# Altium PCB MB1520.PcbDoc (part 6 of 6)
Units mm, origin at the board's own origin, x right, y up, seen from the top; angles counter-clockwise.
Board outline 159 x 88 mm, 6 copper layers (Top Layer, Signal Layer 1, Signal Layer 2, Signal Layer 3, Signal Layer 4, Bottom Layer), stack 1.572 mm thick; 473 components, 377 nets, 1832 pads, 1378 vias.
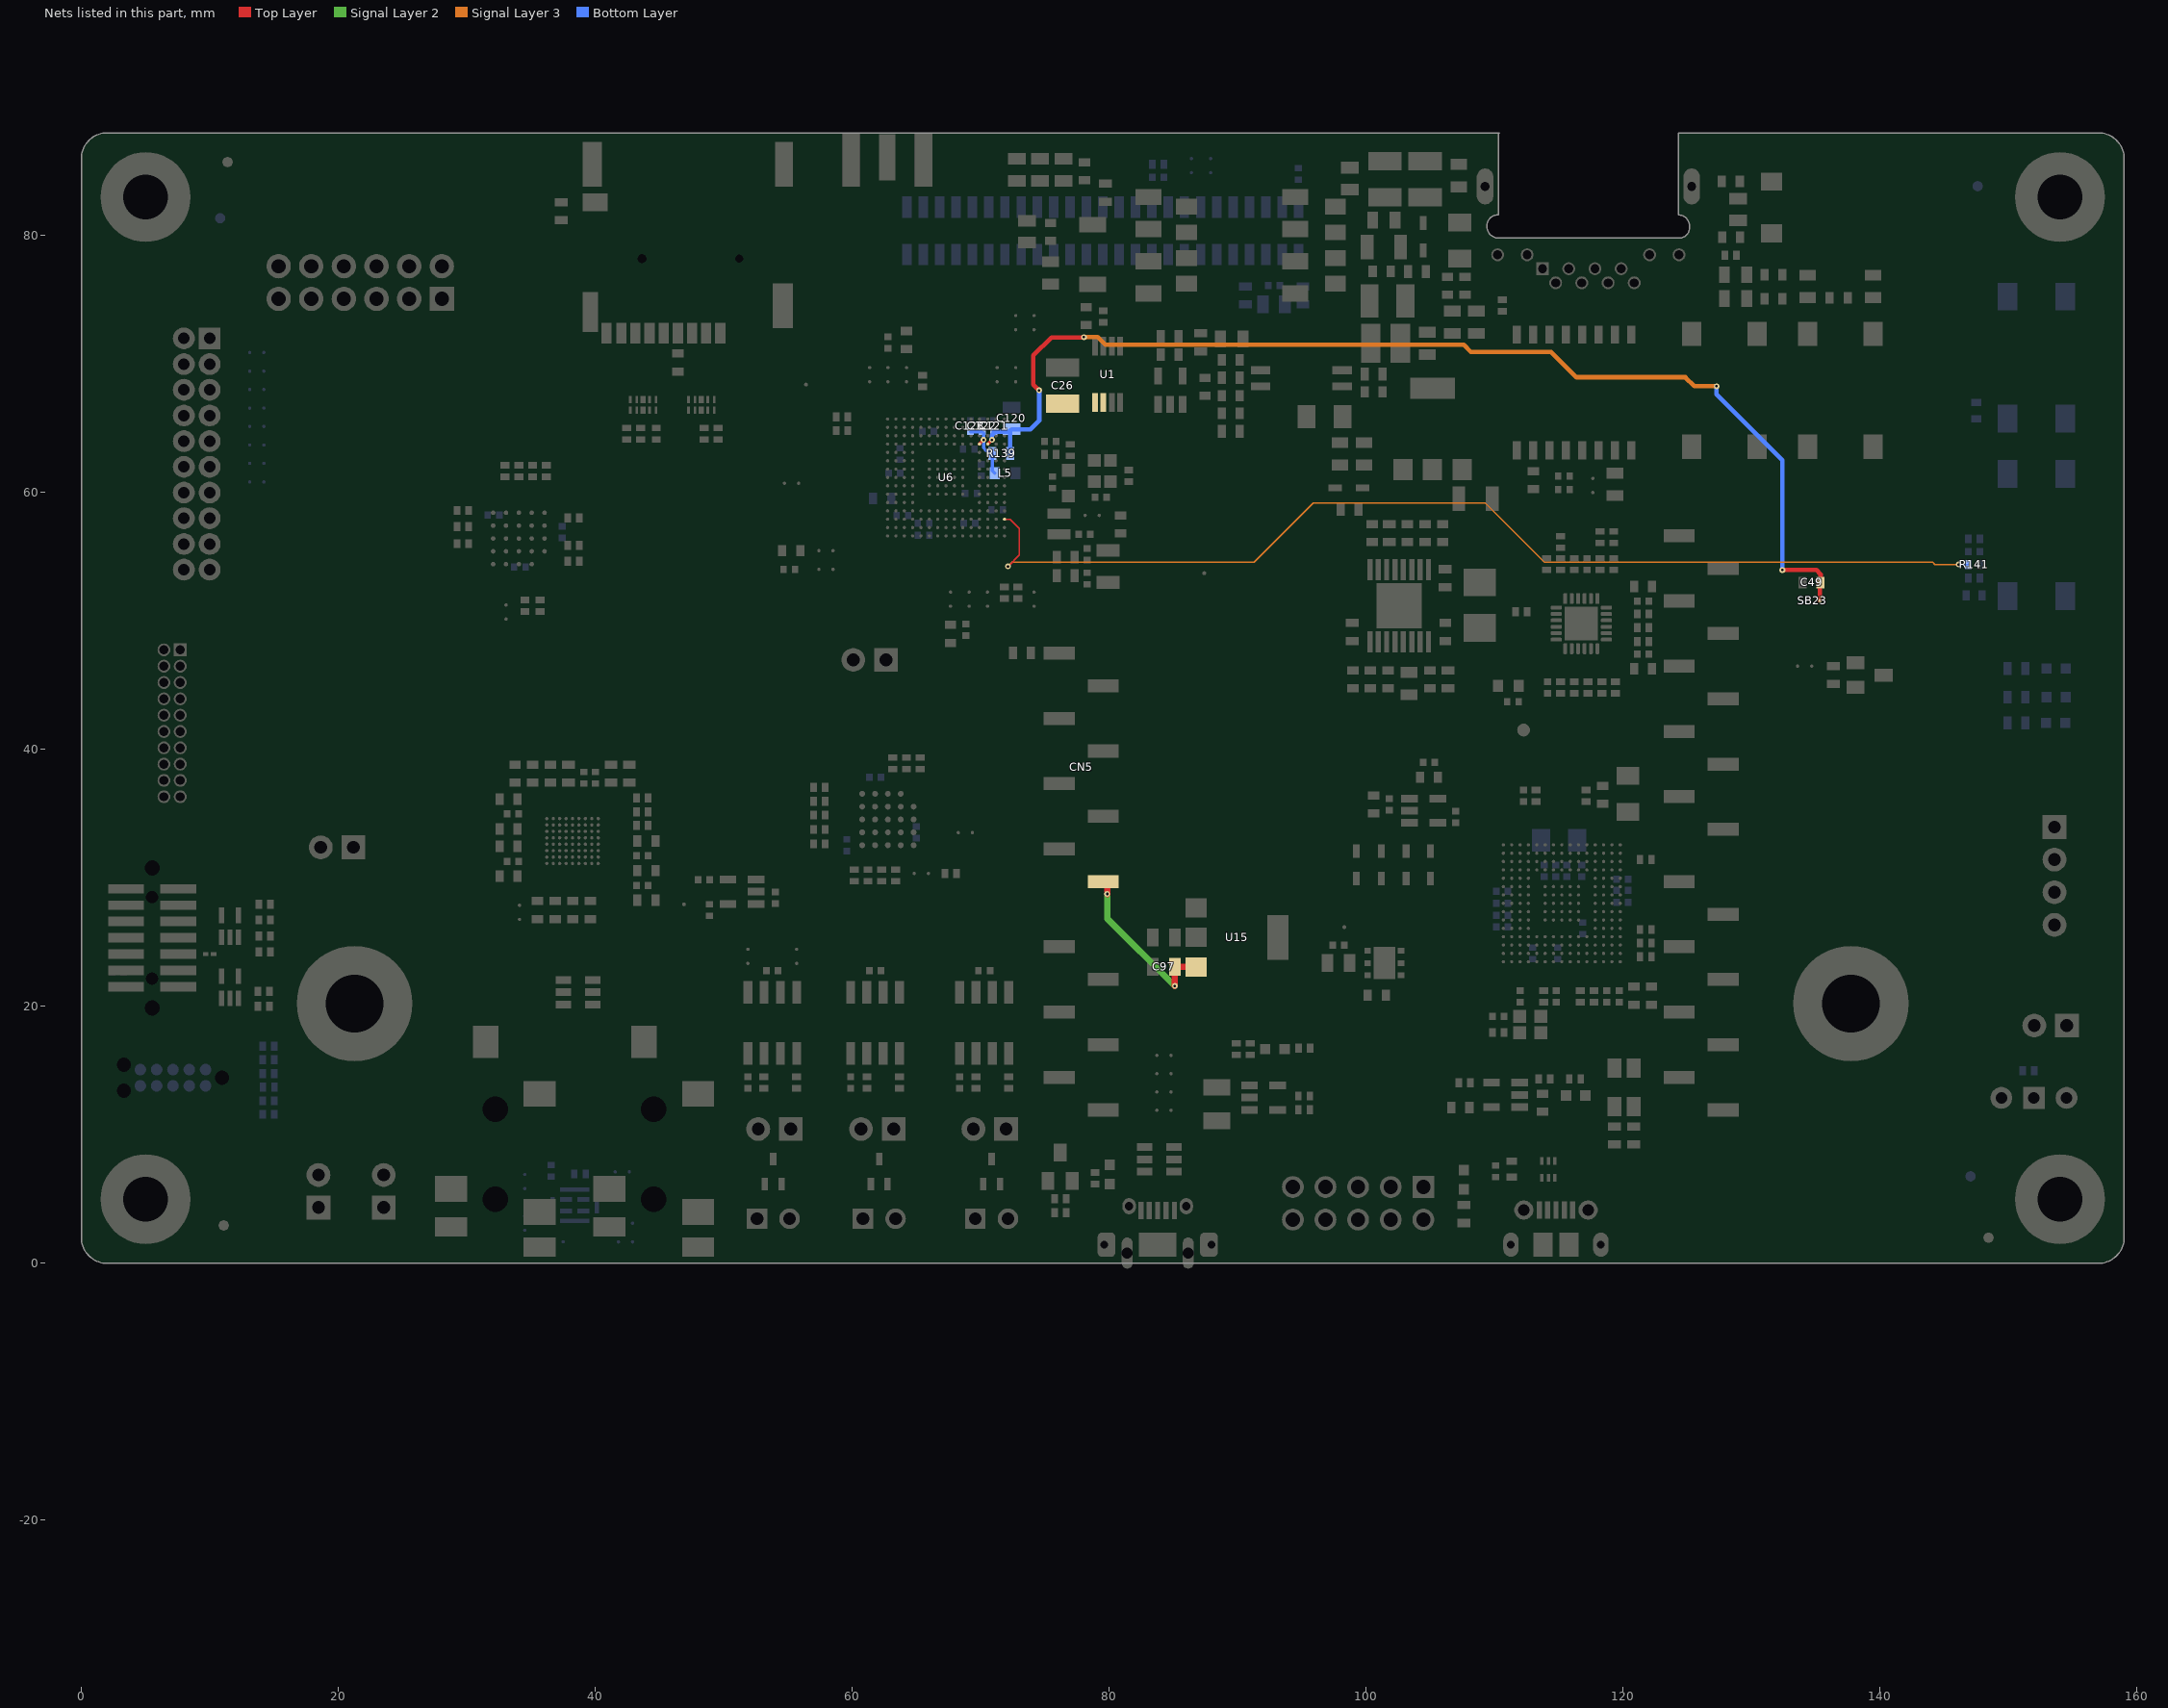
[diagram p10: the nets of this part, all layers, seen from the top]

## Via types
v1: diameter 0.45, hole 0.2, Top Layer to Bottom Layer, tented both sides, 1099 vias
v2: diameter 0.25, hole 0.1, Top Layer to Signal Layer 1, tented both sides, 217 vias
v3: diameter 0.25, hole 0.1, Signal Layer 4 to Bottom Layer, tented both sides, 53 vias
v4: diameter 0.6, hole 0.3, Top Layer to Bottom Layer, tented both sides, 9 vias

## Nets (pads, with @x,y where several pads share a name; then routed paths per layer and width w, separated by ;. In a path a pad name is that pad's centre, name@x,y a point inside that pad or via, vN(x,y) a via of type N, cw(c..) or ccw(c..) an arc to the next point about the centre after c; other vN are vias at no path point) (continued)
VDDA: C122.2 C123.1 L5.2 R139.2 U6.M4 | length 5.2
  Top Layer w0.25: U6.M4@69.9,63.775 v1(70.225,64.1)
  Bottom Layer w0.25: C123.1@69.2,64.725 C122.2@70.125,64.725 70.225,64.625 v1(70.225,64.1) 70.225,63.475 70.432,63.268 70.682,63.268 R139.2@70.9,63.05 70.9,61.7 L5.2@71.1,61.5
VIN: C97.2 CN5.8 U15.3 | length 14
  Top Layer w0.508: CN5.8@79.54,29.72 79.85,29.411 v1(79.85,28.75) ; v1(85.1,21.596) C97.2@85.1,23.475 ; C97.2@85.1,23.075 U15.3@86.775,23.075
  Signal Layer 2 w0.508: v1(79.85,28.75) 79.85,26.846 v1(85.1,21.596)
VREF+: C26.2 C49.2 C120.2 C121.2 R139.1 SB23.2 U1.5 U1.6 U6.M3 | length 89
  Top Layer w0.25: U6.M3@70.55,63.775 v1(70.875,64.1)
  Top Layer w0.35: v1(74.55,67.95) 74.1,68.4 74.1,70.675 75.5,72.075 78,72.075 v1(78.025,72.1) ; v1(132.4,53.975) 135.05,53.975 135.375,53.65 C49.2@135.375,53 135.325,52.95 SB23.2@135.325,51.575
  Signal Layer 3 w0.35: v1(78.025,72.1) 79.1,72.1 79.7,71.5 107.6,71.5 108.15,70.95 114.4,70.95 116.375,68.975 124.85,68.975 125.55,68.275 v1(127.275,68.275)
  Bottom Layer w0.35: v1(70.875,64.1) 70.875,64.45 71.025,64.6 C121.2@71.025,64.725 72.2,64.725 C120.2@72.3,64.825 ; R139.1@72.3,63.05 C120.2@72.3,64.825 ; v1(74.55,67.95) 74.55,65.6 73.875,64.925 C120.2@72.4,64.925 C120.2@72.3,64.825 ; v1(127.275,68.275) 127.275,67.65 132.4,62.525 v1(132.4,53.975)
WAKEUP: R141.2 U6.C1 | length 83.5
  Top Layer w0.1: U6.C1@71.85,57.925 72.275,57.925 73,57.2 73,55.125 v1(72.125,54.25)
  Signal Layer 3 w0.12: v1(72.125,54.25) 72.45,54.575 91.275,54.575 95.875,59.175 109.275,59.175 113.875,54.575 144.1,54.575 144.275,54.4 v1(146.125,54.4)
  Bottom Layer w0.12: v1(146.125,54.4) R141.2@146.875,54.4
pads on no net: CN2.NPTH1 CN2.NPTH2 CN7.0 CN7.1 CN7.2 CN7.9 CN10.2 CN10.5 CN10.7 CN10.MT1 CN10.MT2 CN11.2 CN11.5 CN11.7 CN11.MT1 CN11.MT2 CN14.11 CN14.12 CN15.4 CN19.41 CN19.42 CN19.44 CN19.46 CN19.48 CN20.8 CN20.9 CN20.11 CN20.13 CN20.14 CN20.15 CN20.16 CN20.17 CN20.18 CN21.7 CN21.11 CN21.12 CN21.13 MIRE1.1 MIRE4.1 MIRE5.1 MIRE6.1 MIRE7.1 MIRE8.1 P1.9 P1.10 T3.4 T3.5 T3.12 T3.13 U3.1 U3.2 U5.4 U5.5 U5.6 U5.7 U7.A2 U7.A5 U7.B5 U7.C2 U7.C5 U9.4 U10.A2 U10.A3 U10.B1 U10.B5 U10.C5 U12.A6 U12.A8 U12.B4 U12.B5 U12.B8 U12.B9 U12.C4 U12.C5 U12.C7 U12.C8 U12.E1 U12.E5 U12.F4 U12.F5 U12.F6 U12.F8 U12.F9 U12.G4 U12.H2 U12.H3 U12.H4 U12.H5 U13.A1 U13.A2 U13.A3 U13.A4 U13.A5 U13.A6 U13.A8 U13.A9 U13.A10 U13.A11 U13.A12 U13.A13 U13.B1 U13.B2 U13.B3 U13.B4 U13.B5 U13.B6 U13.B7 U13.B8 U13.B9 U13.B10 U13.B11 U13.B12 U13.B13 U13.B14 U13.B15 U13.C2 U13.C3 U13.C4 U13.C11 U13.C12 U13.C13 U13.C14 U13.C15 U13.D1 U13.D2 U13.D3 U13.D4 U13.D10 U13.D11 U13.D13 U13.D14 U13.E1 U13.E2 U13.E3 U13.E4 U13.E12 U13.E13 U13.E14 U13.E15 U13.F1 U13.F4 U13.F14 U13.G4 U13.G14 U13.G15 U13.H1 U13.H2 U13.H3 U13.H4 U13.H14 U13.H15 U13.J2 U13.J3 U13.J4 U13.K1 U13.K2 U13.K3 U13.K12 U13.K14 U13.K15 U13.L1 U13.L3 U13.L12 U13.L13 U13.L14 U13.L15 U13.M2 U13.M3 U13.M4 U13.M5 U13.M6 U13.M7 U13.M12 U13.M13 U13.M14 U13.M15 U13.N2 U13.N4 U13.N5 U13.N6 U13.N7 U13.N11 U13.N13 U13.N14 U13.N15 U13.P2 U13.P4 U13.P5 U13.P6 U13.P7 U13.P8 U13.P9 U13.P10 U13.P11 U13.P12 U13.P13 U13.P14 U13.P15 U13.R2 U13.R3 U13.R6 U13.R7 U13.R8 U13.R9 U13.R10 U13.R11 U13.R12 U13.R13 U17.1 U17.4 U17.5 U25.5 U29.4 U33.6 U33.7 U33.8

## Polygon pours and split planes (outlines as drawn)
VREF+ on Top Layer "NO_TH" (solid, remove dead copper, pour order 14): 79.55,68.275 79.825,68 79.825,66.15 79.575,65.9 74.475,65.9 74.15,66.225 74.15,67.95 74.475,68.275
POE7 on Top Layer "NO_TH" (solid, remove dead copper, pour order 12): 81.5,66.05 81.5,69.6 80.75,70.35 78.65,70.35 77.475,71.525 77.475,73.425 77.775,73.725 80.025,73.725 80.2,73.9 80.2,74.575 79.675,75.1 76.95,75.1 74.55,72.7 74.55,69.125 75.225,68.45 79.675,68.45 79.925,68.2 79.925,66.125 80.1,65.95 81.4,65.95
3V3 on Top Layer "NO_TH" (solid, remove dead copper, pour order 58): 99.85,23.825 99.2,24.475 99.2,25.7 99.035,25.865 97.94,25.865 97.85,25.775 97.85,22.45 98.025,22.275 99.075,22.275 99.75,22.95 100.35,22.95 100.475,23.075 100.475,23.675 100.325,23.825
5V on Top Layer "NO_TH" (solid, remove dead copper, pour order 60): 100.425,21.65 100.725,21.35 100.725,20.225 100.45,19.95 99.125,19.95 98.875,20.2 98.875,21.875 99.775,22.775 100.3,22.775 100.425,22.65
POE4 on Top Layer "NO_TH" (solid, remove dead copper, pour order 2): 92.6,76.525 95.875,76.525 96.575,77.225 99.375,77.225 100.1,77.95 100.975,77.95 101.3,77.625 101.3,70.15 101.15,70 99.5,70 95.25,74.25 92.675,74.25 92.25,74.675 92.25,76.175
NetC73_1 on Top Layer "NO_TH" (solid, remove dead copper, pour order 0): 106.075,32.725 105.55,33.25 100.375,33.25 99.7,33.925 99.7,35.325 100.1,35.725 104.3,35.725 104.475,35.9 104.475,36.728 104.486,36.739 104.076,37.15 99.4,37.15 98.225,35.975 98.225,31.625 98.6,31.25 98.797,31.25 105.875,31.25 105.875,31.275 106.075,31.475
POE7 on Top Layer "NO_TH" (solid, remove dead copper, pour order 4): 87.125,79.275 81.45,79.275 80.875,79.85 80.875,84.65 80.275,85.25 71.975,85.25 71.525,85.7 71.525,86.675 72.1,87.25 84.575,87.25 87.525,84.3 87.525,79.675
POE5 on Top Layer "NO_TH" (solid, remove dead copper, pour order 6): 87.6,75.7 87.6,78.55 87,79.15 86.975,79.125 78.4,79.125 76.375,77.1 74.825,77.1 74.35,76.625 74.35,75.675 74.825,75.2 80.45,75.2 81.25,74.4 86.3,74.4 87.225,75.325
NetC11_2 on Top Layer "NO_TH" (solid, remove dead copper, pour order 8): 72.5,80.45 76.875,80.45 77.35,79.975 79.8,79.975 80.6,80.775 80.6,82.95 80.35,83.2 78.525,83.2 77.4,82.075 72.85,82.075 72.3,81.525 72.3,80.65
5V_POE on Top Layer "NO_TH" (solid, remove dead copper, pour order 10): 80.275,83.375 80.65,83.75 80.65,84.5 80.275,84.875 71.925,84.875 71.625,84.575 71.625,83.425 72,83.05 77.95,83.05 78.275,83.375
POE7 on Top Layer "POE7" (solid, remove dead copper, pour order 62): -4.2,1.825 -0.275,-2.1 158.55,-2.1 161.55,0.925 161.55,86.625 158.3,89.875 -1.95,89.875 -4.2,87.625
POE7 on Signal Layer 3 "POE7" (solid, remove dead copper, pour order 56): 1.2,91.4 157.075,91.4 160.6,87.875 160.6,0.575 156.55,-3.475 1.2,-3.475 -2.6,0.325 -2.6,87.6
AGND on Signal Layer 3 "NO_TH" (solid, remove dead copper, pour order 18): 106.75,51.475 105.85,51.475 105.55,51.775 105.55,52.846 104.546,53.85 100.125,53.85 99.6,53.325 99.6,49.025 100.775,47.85 100.775,43.05 100.525,42.8 98.825,42.8 98.336,43.289 98.336,56.186 101.025,58.875 105.25,58.875 106.45,57.675 106.45,53.45 107,52.9 107,51.725
NetC9_2 on Signal Layer 3 "NO_TH" (solid, remove dead copper, pour order 16): 100.25,53.55 104.3,53.55 105.326,52.524 105.326,50.974 107.775,48.525 107.775,43.7 107,42.925 101.475,42.925 101.075,43.325 101.075,48 99.975,49.1 99.975,53.275
POE1 on Signal Layer 1 "NO_TH" (solid, remove dead copper, pour order 22): 96.4,89.225 96.4,85.278 95.147,84.025 91.725,84.025 91.1,83.4 91.1,74.075 96.725,68.45 96.725,58.175 98.325,56.575 98.325,43.3 98.825,42.8 107.325,42.8 108.7,44.175 108.7,56.1 110.75,58.15 110.75,61.25 108.98,63.02 108.98,67.845 105.975,70.85 105.975,89.225
POE7 on Signal Layer 1 "POE7" (solid, remove dead copper, pour order 26): -0.5,89.1 158.625,89.1 161.55,86.175 161.55,-0.15 159.5,-2.2 0.45,-2.2 -2.725,0.975 -2.725,86.875
3V3 on Signal Layer 2 "3V3" (solid, remove dead copper, pour order 54): 159.225,89.225 160.875,87.575 160.875,-0.05 156.725,-4.2 1.425,-4.2 -2.025,-0.75 -1.275,0 -1.275,88.725 -0.775,89.225
5V_POE on Signal Layer 2 "5V_PoE" (solid, remove dead copper, pour order 50): 75.775,84.25 76.15,83.875 76.15,74.1 78.75,71.5 83.7,71.5 85.575,73.375 94.85,73.375 95.75,72.35 95.75,39.25 104.025,30.975 104.025,17.05 100.675,13.7 100.675,10.475 99.9,9.7 99.2,9.7 98.85,10.05 98.85,13.5 102.675,17.325 102.675,29.85 93.825,38.7 93.825,70.4 92.675,71.525 86.075,71.525 84.475,69.85 75.175,69.85 72.675,72.35 72.675,83.925 73,84.25
5V on Signal Layer 2 "5V" (solid, remove dead copper, pour order 52): 71.1,32.15 76.625,37.675 76.625,38.525 76.35,38.8 75.85,38.8 69.675,32.625 69.675,29.675 67.25,27.25 64.65,27.25 52.775,27.25 50.8,25.275 50.8,23.775 53.875,20.7 62.7,20.7 68.6,14.8 68.6,9.8 65.775,6.975 15.25,6.975 1.175,21.05 1.175,29.1 3.725,31.65 3.725,49.1 5.75,51.125 9.275,51.125 12.075,53.925 12.075,79.475 18.575,85.975 77.65,85.975 79.325,84.3 79.325,73.4 80.5,72.225 81.725,72.225 85.375,75.875 90.95,75.875 92.425,77.35 92.425,86.4 90.075,88.75 0.425,88.75 -0.3,88.025 -0.3,0.425 2.275,-2.15 124.55,-2.15 127.225,0.525 127.225,26.25 124.6,28.875 122.25,28.875 121.6,28.225 121.6,25.95 124.175,23.375 124.175,17.025 121.975,14.825 104.9,14.825 103.625,13.55 103.625,8.525 101.9,6.8 91.25,6.8 87.5,3.05 73.475,3.05 71.1,5.425
VDD_SDC on Signal Layer 2 "VDD_SDC" (solid, remove dead copper, pour order 44): 52.75,57.675 55.65,57.675 56.025,57.3 56.025,53.825 56.225,53.625 61.45,53.625 61.675,53.85 61.675,61.075 64.7,64.1 67.525,64.1 69.1,62.525 69.1,49.5 69.225,49.375 70.325,49.375 70.325,49.5 71.575,50.775 71.575,56.2 73.95,58.575 75.475,58.575 75.675,58.6 77.725,60.65 78.65,60.65 79.05,61.05 79.05,62.544 77.644,63.95 72.825,63.95 69.425,67.35 67.25,67.35 63.775,70.825 61.8,72.8 59.9,72.8 59.025,71.9 59.025,66.95 56.25,64.175 52.825,64.175 51.125,62.475 51.125,59.3
VDD_MCU on Signal Layer 2 "VDD_MCU" (solid, remove dead copper, pour order 42): 61.525,48.717 64.533,51.725 66.521,51.725 66.9,52.104 66.9,52.425 61.65,57.675 59.4,57.675 57.425,59.65 53.875,59.65 52.975,60.55 52.975,61 53.35,61.375 60.15,61.375 60.75,61.975 60.75,71.15 61.025,71.425 61.4,71.425 61.65,71.175 61.65,66.275 63.275,64.65 69.475,64.65 69.875,64.25 69.875,63.625 71.45,62.05 77.825,62.05 78.025,61.85 78.025,61.55 77.8,61.325 70.925,61.325 70.725,61.125 70.725,58.25 70.1,57.625 69.45,57.625 69,57.15 69,51.025 63.58,45.605 61.82,45.605 61.525,45.9
USB_FS_VBUS on Signal Layer 2 "USB_FS_VBUS" (solid, remove dead copper, pour order 40): 61.7,42.2 74.725,42.2 77.15,39.775 77.15,11.525 76.55,10.925 76.55,4.125 77.3,3.325 86.925,3.325 90.725,7.125 101.425,7.125 102.725,8.425 102.725,13.55 105.6,16.425 105.6,29.075 105.15,29.525 105.125,29.5 104.636,29.5 104.225,29.089 104.225,16.95 100.875,13.6 100.875,10.375 98.675,8.175 89.65,8.175 88.6,9.225 88.6,15.175 88.275,15.5 87.6,15.5 87.225,15.125 87.225,9.05 86.1,7.925 80.725,7.925 79.575,6.775 78.7,6.775 78.025,7.45 78.025,10.3 78.625,10.9 78.625,40.45 75.75,43.325 63.875,43.325 58.3,43.325 54.925,46.7 54.925,55.225 53.925,56.225 53.5,56.225 53.275,56 53.275,46.675 57.75,42.2
3V3_STLK on Signal Layer 2 "3V3_STLK" (solid, remove dead copper, pour order 32): 105.025,39.925 105.6,39.925 105.85,39.675 105.85,34.375 107.95,32.275 117.675,32.275 118.5,31.45 119.7,31.45 147.925,31.45 151.85,35.375 154.181,35.375 155.025,34.531 155.025,33.15 154.45,32.575 152.025,32.575 149.25,29.8 120,29.8 119.375,29.175 119.375,23.25 120.225,22.4 123.5,22.4 123.775,22.125 123.775,21.575 123.439,21.239 120.301,21.239 119.775,20.714 119.775,16.3 119.475,16 119.025,16 118.725,16.3 118.725,19.475 117.65,20.55 113.025,20.55 109.7,17.225 109.025,17.225 108.65,17.6 108.675,17.625 108.675,18.7 110.875,20.9 110.875,29.7 109.775,30.8 107.4,30.8 104.85,33.35 104.85,39.75
E5V on Signal Layer 2 "E5V" (solid, remove dead copper, pour order 38): 76.875,46.775 80.8,42.85 80.8,35.3 80.775,35.3 87.925,28.15 99.875,28.15 101,29.275 101.375,29.275 101.525,29.125 101.525,28.7 99.375,26.55 97.875,26.55 95.75,24.425 95.75,15.925 97.15,14.525 97.15,10.175 97,10.025 96.7,10.025 96.2,10.525 96.2,13.975 94.4,15.775 94.4,21.775 90.725,25.45 85.025,25.45 84.15,26.325 84.15,29.85 79.425,34.575 79.425,42.475 76.425,45.475 73.175,45.475 72.925,45.725 72.925,46.525 73.175,46.775
1V8 on Signal Layer 2 "1V8" (solid, remove dead copper, pour order 30): 47.675,27.575 45.975,29.275 41.45,29.275 39,31.725 34.625,31.725 34.475,31.875 34.475,32.3 35.325,33.15 35.325,34.325 34.625,35.025 34.625,35.425 34.8,35.6 36.725,35.6 42.25,30.075 46.675,30.075 48.45,28.3 48.45,27.75 48.275,27.575
NetC34_1 on Signal Layer 2 "NO_TH" (solid, remove dead copper, pour order 24): 112.175,43.225 119.05,43.225 120.775,44.95 120.775,47.9 120.325,48.35 119.3,48.35 117.85,46.9 113.925,46.9 111.9,44.875 111.9,43.5
POE7 on Signal Layer 4 "POE7" (solid, remove dead copper, pour order 28): 0.2,88.775 159.9,88.775 161.025,87.65 161.025,0.625 159.225,-1.175 -0.4,-1.175 -1.575,0 -1.575,87
POE1 on Signal Layer 4 "NO_TH" (solid, remove dead copper, pour order 20): 96.4,89.225 96.4,85.278 95.147,84.025 91.725,84.025 91.1,83.4 91.1,74.075 96.725,68.45 96.725,58.175 98.325,56.575 98.325,43.3 98.825,42.8 107.325,42.8 108.7,44.175 108.7,56.1 110.75,58.15 110.75,61.25 108.98,63.02 108.98,67.845 105.975,70.85 105.975,89.225
POE7 on Bottom Layer "POE7" (solid, remove dead copper, pour order 36): 0.275,88.7 159.475,88.7 160.575,87.6 160.575,-0.15 159.05,-1.675 1.175,-1.675 -0.925,0.425 -0.925,87.35 -0.925,87.5
5V_USB_CHGR on Bottom Layer "5V_USB_CHGR" (solid, remove dead copper, pour order 34): 118.125,8.3 118.125,15.425 117.925,15.625 117.275,15.625 117.075,15.425 117.075,9.425 116.025,8.375 114.825,7.175 109.4,7.175 108.775,7.8 108.775,15.45 107.15,17.075 107.15,29.3 105.7,30.75 99.475,30.75 98.575,29.85 98.575,28.7 98.75,28.525 99.675,28.525 100.95,29.8 105.2,29.8 105.85,29.15 105.85,15.2 107.575,13.475 107.575,9.575 106.15,8.15 93.6,8.15 92.605,7.155 92.605,4.945 93.375,4.175 106.2,4.175 107.425,5.4 115.225,5.4

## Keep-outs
Keep-Out Layer:
  rectangle: 136.4,2.168 144.9,4.143

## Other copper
Top Layer:
  rectangle net POE7: 81.471,79.873 84.62,81.143
  rectangle net POE7: 81.471,82.372 84.62,83.642
  rectangle net POE1: 92.901,82.372 96.05,83.642
  rectangle net POE2: 92.901,79.873 96.05,81.143
  rectangle net POE3: 92.901,77.373 96.05,78.643
  rectangle net POE4: 92.901,74.873 96.05,76.143
  rectangle net POE5: 81.471,74.873 84.62,76.143
  rectangle net POE5: 81.471,77.373 84.62,78.643
  rectangle net POE1: 105.575,53.453 106.744,54.621
  rectangle net AGND: 105.575,52.053 106.744,53.221
  text "1" at 136.693,2.571 h2
  text ".Layer_Name" at 36.253,-23.408 h3
  text ".GTL" at 77.948,-23.408 h3
Signal Layer 1:
  text "2" at 137.943,2.571 h2
  text ".Layer_Name" at 36.253,-23.408 h3
  text ".G1" at 77.948,-23.408 h3
Signal Layer 2:
  text "3" at 139.443,2.571 h2
  text ".Layer_Name" at 36.253,-23.408 h3
  text ".G2" at 77.948,-23.408 h3
Signal Layer 3:
  text "4" at 141.693,2.571 h2
  text ".Layer_Name" at 36.285,-23.391 h3
  text ".G3" at 77.98,-23.391 h3
Signal Layer 4:
  text "5" at 143.193,2.571 h2
  text ".Layer_Name" at 36.285,-23.391 h3
  text ".G4" at 77.98,-23.391 h3
Bottom Layer:
  text "6" at 144.693,2.571 h2
  text ".GBL" at 66.745,-23.44 h3
  text ".Layer_Name" at 108.059,-23.44 h3

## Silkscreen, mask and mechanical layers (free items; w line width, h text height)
Top Overlay:
  lines w0.1: 2.675,31.925 2.675,33.45 8.35,33.45 8.35,31.925 2.675,31.925 ; 12.224,59.926 12.224,66.426 14.574,66.426 14.574,59.926 12.224,59.926 ; 17.625,8.433 19.325,8.433 19.325,14.5 17.625,14.5 17.625,8.433 ; 19.125,71.1 23.9,71.1 23.9,72.775 19.125,72.775 19.125,71.1 ; 22.775,8.55 24.3,8.55 24.3,13.875 22.775,13.875 22.775,8.55 ; 25.625,7.725 27.15,7.725 27.15,14.15 25.625,14.15 25.625,7.725 ; 26.575,26.3 26.575,29 32.05,29 32.05,26.3 26.575,26.3 ; 36.9,83.975 36.9,87.25 38.425,87.25 38.425,83.975 36.9,83.975 ; 38.175,51.775 38.175,53.5 45.234,53.5 45.234,51.775 38.175,51.775 ; 38.25,9.65 39.775,9.65 39.775,14.85 38.25,14.85 38.25,9.65 ; 50.9,0.325 50.9,1.85 56.925,1.85 56.925,0.325 50.9,0.325 ; 55.425,38.35 55.425,39.875 61.775,39.875 61.775,38.35 55.425,38.35 ; 56.95,81.65 56.95,87.05 58.475,87.05 58.475,81.65 56.95,81.65 ; 59.2,0.35 59.2,1.775 65.225,1.775 65.225,0.35 59.2,0.35 ; 67.925,0.35 67.925,1.875 73.95,1.875 73.95,0.35 67.925,0.35 ; 88.75,0.275 90.275,0.275 90.275,5.425 88.75,5.425 88.75,0.275 ; 91.05,1.65 92.575,1.65 92.575,7.45 91.05,7.45 91.05,1.65 ; 119.625,0.675 119.625,2.2 123.4,2.2 123.4,0.675 119.625,0.675 ; 126.3,86.125 126.3,87.65 133.8,87.65 133.8,86.125 126.3,86.125
  lines w0.152: 2.127,73.12 2.458,73.12 ; 2.254,52.8 2.585,52.8 ; 2.889,73.12 3.22,73.12 ; 3.016,52.8 3.347,52.8 ; 3.931,73.12 4.261,73.12 ; 4.058,52.8 4.388,52.8 ; 4.693,73.12 5.023,73.12 ; 4.82,52.8 5.15,52.8 ; 5.607,52.8 6.674,52.8 ; 5.633,53.283 5.633,54.349 ; 5.633,55.264 5.633,56.331 ; 5.633,57.321 5.633,58.388 ; 5.633,59.252 5.633,60.318 ; 5.633,61.233 5.633,62.3 ; 5.633,63.189 5.633,64.255 ; 5.633,65.373 5.633,66.44 ; 5.633,67.405 5.633,68.472 ; 5.633,69.335 5.633,70.402 ; 5.633,71.367 5.633,72.434 ; 5.633,73.12 6.699,73.12 ; 7.207,52.825 8.274,52.825 ; 7.207,73.12 8.274,73.12 ; 8.935,52.825 10.001,52.825 ; 9.011,73.12 10.078,73.12 ; 10.89,73.12 11.199,73.126 ; 10.916,52.8 11.326,52.806 ; 11.377,54.172 11.377,55.238 ; 11.377,56 11.377,57.067 ; 11.377,58.032 11.377,59.099 ; 11.377,59.988 11.377,61.055 ; 11.377,61.969 11.377,63.036 ; 11.377,63.925 11.377,64.992 ; 11.377,65.932 11.377,66.999 ; 11.377,67.786 11.377,68.853 ; 11.377,69.615 11.377,70.682 ; 11.377,71.52 11.377,72.587 ; 13.7,74.367 13.7,73.3 14.767,73.3 ; 13.7,75.332 13.7,76.399 ; 13.7,77.288 13.7,78.355 ; 13.7,80.336 13.7,79.269 14.767,79.269 ; 13.7,81.225 13.7,82.292 ; 13.7,83.231 13.7,84.298 ; 13.7,85.086 13.7,86.152 ; 15.732,73.3 16.799,73.3 ; 15.732,79.269 16.799,79.269 ; 17.688,73.3 18.755,73.3 ; 17.688,79.269 18.755,79.269 ; 19.669,73.3 20.736,73.3 ; 19.669,79.269 20.736,79.269 ; 21.625,73.3 22.692,73.3 ; 21.625,79.269 22.692,79.269 ; 23.631,73.3 24.698,73.3 ; 23.631,79.269 24.698,79.269 ; 25.486,73.3 26.552,73.3 ; 25.486,79.269 26.552,79.269 ; 27.314,73.3 28.381,73.3 ; 27.314,79.269 28.381,79.269 ; 29.219,73.3 29.575,73.3 ; 29.219,79.269 29.575,79.269 ; 29.575,73.323 29.575,74.389 ; 29.575,75.177 29.575,76.244 ; 29.575,77.183 29.575,78.25 ; 29.575,79.139 29.575,80.206 ; 29.575,81.12 29.575,82.187 ; 29.575,83.076 29.575,84.143 ; 29.575,85.108 29.575,86.175
  text "ETHERNET" at 126.475,86.412 h1.5
  text "µSD" at 38.05,84.45 h1.5 r90
  text "ADC_IN" at 58.075,81.775 h1.5 r90
  text "P1" at 30.075,76.3 h1.2
  text "PMOD" at 19.6,71.475 h1.5
  text "STMOD+" at 13.824,60.526 h1.5 r90
  text "D15" at 129.5,56.175 h1.5
  text "C" at 138.35,55 h12
  text "D14" at 129.5,53.625 h1.5
  text "HyperRAM" at 38.575,52.225 h1.5
  text "P2" at 2.85,51.575 h1.2
  text "AVDD" at 129.5,51.125 h1.5
  text "GND" at 129.5,48.575 h1.5
  text "E5V" at 81,47.1 h1.5
  text "D13" at 129.5,46 h1.5
  text "IOREF" at 81,44.55 h1.5
  text "D12" at 129.5,43.475 h1.5
  text "NRST" at 81,42.025 h1.5
  text "D11" at 129.5,40.85 h1.5
  text "E" at 143.15,40.825 h11
  text "I" at 150.675,40.075 h12
  text "3V3" at 81,39.425 h1.5
  text "OCTOSPI" at 55.6,38.6 h1.5
  text "D10" at 129.5,38.4 h1.5
  text "5V" at 81,36.875 h1.5
  text "D9" at 129.5,35.875 h1.5
  text "GND" at 81,34.25 h1.5
  text "K" at 134.45,34.2 h12
  text "3V3" at 149.5,33.4 h1.5
  text "D8" at 129.5,33.325 h1.5
  text "STDC14" at 3,32.225 h1.5
  text "GND" at 81,31.675 h1.5
  text "SWCLK" at 147.3,31.025 h1.5
  text "D7" at 129.5,29.325 h1.5
  text "VIN" at 81,29.3 h1.5
  text "GND" at 149.05,28.5 h1.5
  text "D6" at 129.5,26.675 h1.5
  text "AUDIO / CODEC" at 26.95,26.525 h1.5
  text "H" at 134.35,25.95 h12
  text "SWDIO" at 147.525,25.8 h1.5
  text "A0" at 81,24.275 h1.5
  text "D5" at 129.5,24.15 h1.5
  text "A1" at 81,21.6 h1.5
  text "D4" at 129.5,21.575 h1.5
  text "D3" at 129.5,19.075 h1.5
  text "A2" at 81,19.05 h1.5
  text "A3" at 81,16.525 h1.5
  text "D2" at 129.5,16.525 h1.5
  text "D1" at 129.5,14.05 h1.5
  text "A4" at 81,14 h1.5
  text "A5" at 81,11.475 h1.5
  text "D0" at 129.5,11.475 h1.5
  text "LINE IN" at 39.475,10 h1.5 r90
  text "SPK left" at 24.025,8.725 h1.5 r90
  text "SPK right" at 18.825,8.575 h1.5 r90
  text "LINE OUT" at 27,7.925 h1.5 r90
  text "CHGR" at 94.875,7.475 h1.5 r90
  text "E5V" at 97.425,7.475 h1.5 r90
  text "POE5V" at 99.975,7.475 h1.5 r90
  text "USBFS" at 102.575,7.475 h1.5 r90
  text "STLK" at 104.925,7.475 h1.5 r90
  text "G" at 130.45,5 h11.4
  text "F" at 142.45,5 h12
  text "5V PWR" at 92.295,2.075 h1.5 r90
  text "STLK" at 119.825,0.925 h1.5
  text "FDCAN3" at 51.4,0.625 h1.5
  text "FDCAN2" at 59.6,0.625 h1.5
  text "FDCAN1" at 68.475,0.625 h1.5
  text "USB FS" at 90,0.5 h1.5 r90
  text ".Layer_Name" at 36.253,-23.408 h3
  text ".GTO" at 77.948,-23.408 h3
Bottom Overlay:
  drawing of 291 lines, arcs and shapes, not listed
  text "PMOD" at 30.3,83.325 h1.5 r270
  text "STMOD+" at 6.25,75.9 h1.5
  text "RST" at 157.175,69.55 h1.5 r270
  text "USER" at 157.1,55.1 h1.5 r270
  text "USER LEDs" at 144.325,40.625 h1.5 r270
  text "MB1299" at 2.875,40.1 h1.5 r270
  text "3V3" at 151.625,33.45 h1.5
  text "SWCLK" at 151.725,30.975 h1.5
  text "CN7" at 7.575,28.875 h1.2 r270
  text "GND" at 151.7,28.5 h1.5
  text "SWDIO" at 151.7,25.95 h1.5
  text "CN6" at 154.7,23.775 h1.2
  text "JP3" at 154.475,20.15 h1.2
  text "STDC14" at 7.375,20.1 h1.5 r270
  text "CN11" at 48.2,10.85 h1.2 r270
  text "CN10" at 27.75,9.825 h1.2 r270
  text "JP4" at 56.875,9.375 h1.2 r270
  text "JP5" at 64.925,9.35 h1.2 r270
  text "JP6" at 73.775,9.35 h1.2 r270
  text "SYS MEM" at 158.694,9.14 h1.5
  text "SPK Right" at 18.95,8.375 h1.5 r270
  text "SPK Left" at 23.05,8.375 h1.5 r270
  text "TAG" at 11.1,8.225 h1.5
  text "J" at 142.45,7.825 h15
  text "JP7" at 104.925,7.625 h1.2
  text "CN14" at 85.3,7.175 h1.2
  text "CN15" at 115.925,7.1 h1.2
  text "MB1520C" at 142.65,6 h1.5
  text "USB FS" at 86.2,5.8 h1.5
  text "STLK" at 116.275,5.775 h1.5
  text "CN12" at 15.85,3.8 h1.2 r270
  text "CN13" at 21.1,3.8 h1.2 r270
  text "CN18" at 73.7,1.85 h1.2 r270
  text "CN16" at 56.6,1.8 h1.2 r270
  text "CN17" at 65,1.8 h1.2 r270
  text "LINE OUT" at 27.675,1.4 h1.5 r270
  text "LINE IN" at 48.275,0.975 h1.5 r270
  text "Power Header" at 103.475,0.8 h1.5
  text "FDCAN1" at 73.25,0.775 h1.5
  text "FDCAN3" at 56.425,0.725 h1.5
  text "FDCAN2" at 64.7,0.725 h1.5
  text ".GBO" at 66.745,-23.44 h3
  text ".Layer_Name" at 108.059,-23.44 h3
Top Paste:
  text ".Layer_Name" at 36.226,-23.398 h3
  text ".GTP" at 77.921,-23.398 h3
Bottom Paste:
  text ".GBP" at 66.636,-23.425 h3
  text ".Layer_Name" at 107.95,-23.425 h3
Top Solder:
  rectangle: 136.4,2.168 144.9,4.143
  rectangle: 92.85,82.321 96.101,83.693
  rectangle: 92.85,79.822 96.101,81.194
  rectangle: 92.85,77.322 96.101,78.694
  rectangle: 92.85,74.823 96.101,76.195
  rectangle: 81.42,74.823 84.671,76.195
  rectangle: 81.42,77.322 84.671,78.694
  rectangle: 81.42,79.822 84.671,81.194
  rectangle: 81.42,82.321 84.671,83.693
  rectangle: 105.525,53.402 106.795,54.672
  rectangle: 105.525,52.002 106.795,53.272
  text ".Layer_Name" at 36.251,-23.473 h3
  text ".GTS" at 77.946,-23.473 h3
Bottom Solder:
  rectangle: 136.4,2.168 144.9,4.168
  text ".GBS" at 66.661,-23.5 h3
  text ".Layer_Name" at 107.975,-23.5 h3
M1-Board Shape:
  lines w0.1: 124.303,88 157,88 cw(c157,86) 159,86 159,2 cw(c157,2) 157,0 2,0 cw(c2,2) 0,2 0,86 cw(c2,86) 2,88 110.367,88 110.303,87.936 110.303,81.611 110.242,81.611 ccw(c110.242,80.772) 109.403,80.772 109.403,80.71 ccw(c110.303,80.71) 110.303,79.811 124.303,79.811 ; 124.303,88.011 cw(c124.303,88.005) 124.308,88.005 ; 124.308,88 124.308,81.61 cw(c124.308,80.742) 125.177,80.742 125.177,80.62 cw(c124.368,80.62) 124.368,79.811 124.303,79.811 ; 124.303,79.811 ccw(c124.303,79.811) 124.303,79.811
M2-Board Dimensions:
  text ".Layer_Name" at 36.253,-23.408 h3
  text ".GM2" at 77.948,-23.408 h3
M14-Top Assembly:
  text ".Layer_Name" at 36.253,-23.408 h3
  text ".GM14" at 77.948,-23.408 h3
M15-Bottom Assembly:
  text ".GM15" at 66.745,-23.44 h3
  text ".Layer_Name" at 108.059,-23.44 h3
Drill Drawing:
  drawing of 445 lines, arcs and shapes, not listed
  text "Layer" at 187.864,152.236 h1.52
  text "Name" at 194.241,152.236 h1.52
  text "Material" at 206.575,152.236 h1.52
  text "Thickness" at 217.658,152.236 h1.52
  text "Constant" at 226.762,152.236 h1.52
  text "Board Layer Stack" at 235.188,152.236 h1.52
  text "PCB SPECIFICATIONS :" at 0.825,151.404 h3
  text "PCB : TYPE 3" at 149.237,151.172 h3
  text "Top Overlay" at 194.241,149.188 h1.52
  text "A.   MATERIAL :" at 0.825,147.404 h3
  text "FR-4" at 39.325,147.404 h3
  text "TG-170" at 55.825,147.404 h3
  text "X  TG-150" at 74.075,147.404 h3
  text "TG-140" at 90.075,147.404 h3
  text "Top Solder" at 194.241,146.14 h1.52
  text "Solder Resist" at 206.575,146.14 h1.52
  text "0,015mm" at 217.658,146.14 h1.52
  text "3.5" at 226.762,146.14 h1.52
  text "ASPECT-RATIO, AXE Z :" at 149.237,145.672 h3
  text "B.   MATERIAL FAMILY :" at 0.825,144.404 h3
  text "N/A" at 39.325,144.404 h3
  text "1" at 187.864,143.092 h1.52
  text "Top Layer" at 194.241,143.092 h1.52
  text "0,042mm" at 217.658,143.092 h1.52
  text "C.   SOLDERMASK COLOR :" at 0.825,141.404 h3
  text "GREEN" at 39.325,141.404 h3
  text "WHITE" at 55.825,141.404 h3
  text "X  BLUE" at 74.075,141.404 h3
  text "BLACK" at 90.075,141.404 h3
  text "Dielectric1" at 194.241,140.044 h1.52
  text "FR-4" at 206.575,140.044 h1.52
  text "0,099mm" at 217.658,140.044 h1.52
  text "4.2" at 226.762,140.044 h1.52
  text "6:1 to 8:1 / LEVEL \"B\"" at 149.255,138.924 h3
  text "D.   SILKSCREEN COLOR :" at 0.825,138.404 h3
  text "X  WHITE" at 39.325,138.404 h3
  text "YELLOW" at 55.825,138.404 h3
  text "BLACK" at 74.075,138.404 h3
  text "Blue ink PANTONE 2955" at 90.075,138.404 h3
  text "2" at 187.862,136.996 h1.52
  text "Signal Layer 1" at 194.241,136.996 h1.52
  text "0,035mm" at 217.658,136.996 h1.52
  text "E.   SURFACE FINISH :" at 0.825,135.404 h3
  text "X  ENIG" at 39.325,135.404 h3
  text "IMMERSION SILVER" at 55.825,135.404 h3
  text "IMMERSION TIN" at 90.075,135.404 h3
  text "Dielectric 2" at 194.241,133.948 h1.52
  text "0,102mm" at 217.658,133.948 h1.52
  text "4.2" at 226.762,133.948 h1.52
  text "MINIMUM PARAMETERS" at 149.282,133.323 h3
  text "HASL" at 39.325,132.404 h3
  text "HASL (PB-FREE)" at 55.825,132.404 h3
  text "GOLDEN FINGER" at 90.075,132.404 h3
  text "3" at 187.864,130.9 h1.52
  text "Signal Layer 2" at 194.241,130.9 h1.52
  text "0,035mm" at 217.658,130.9 h1.52
  text "F.   IMPEDANCE CONTROL :" at 0.825,129.404 h3
  text "NO" at 39.325,129.404 h3
  text "X  YES  (SEE IMPEDANCE TABLE FOR DETAIL INFORMATION)" at 55.825,129.404 h3
  text "Dielectric 3" at 194.241,127.852 h1.52
  text "FR-4" at 206.575,127.852 h1.52
  text "0,946mm" at 217.658,127.852 h1.52
  text "4.2" at 226.762,127.852 h1.52
  text "DEFAULT" at 149.282,127.823 h3
  text "G.   THROUGH VIA :" at 0.825,126.404 h3
  text "PLUG THE VIAS WHICH ARE COVERED WITH SOLDERMASK ONE OR TWO SIDE." at 39.325,126.404 h3
  text "4" at 187.864,124.804 h1.52
  text "Signal Layer 3" at 194.241,124.804 h1.52
  text "0,035mm" at 217.658,124.804 h1.52
  text "PLUG MATERIAL :" at 39.325,123.404 h3
  text "X  SOLDERMASK" at 64.825,123.404 h3
  text "NON-CONDUCTIVE EPOXY." at 90.075,123.404 h3
  text "TRACKS : 0.12mm           / GAPS : 0.12mm" at 149.282,122.073 h3
  text "Dielectric 4" at 194.241,121.756 h1.52
  text "0,102mm" at 217.658,121.756 h1.52
  text "4.2" at 226.762,121.756 h1.52
  text "H.   STACK-UP :" at 0.825,120.404 h3
  text "SEE LAYER STACK-UP SEQUENCE FOR OVERALL THICKNESS." at 39.325,120.404 h3
  text "5" at 187.864,118.708 h1.52
  text "Signal Layer 4" at 194.241,118.708 h1.52
  text "0,035mm" at 217.658,118.708 h1.52
  text "MCU / BGA" at 149.3,116.525 h3
  text "Dielectric 5" at 194.241,115.66 h1.52
  text "FR-4" at 206.575,115.66 h1.52
  text "0,099mm" at 217.658,115.66 h1.52
  text "4.2" at 226.762,115.66 h1.52
  text "« THE COMPONENTS WITH PLATED THROUGH HOLE (PTH) MAY BE WELDED (CABLED) IN \"PIN-IN-PASTE\" MODE (IF NECESSARY) »" at 12.8,113.85 h2
  text "6" at 187.864,112.612 h1.52
  text "Bottom Layer" at 194.241,112.612 h1.52
  text "0,042mm" at 217.658,112.612 h1.52
  text "TRACKS : 0.09mm           / GAPS : 0.08mm" at 149.3,110.775 h3
  text "Bottom Solder" at 194.241,109.564 h1.52
  text "Solder Resist" at 206.575,109.564 h1.52
  text "0,015mm" at 217.658,109.564 h1.52
  text "3.5" at 226.762,109.564 h1.52
  text "Bottom Overlay" at 194.241,106.516 h1.52
  text "Symbol" at 176.445,95.491 h3
  text "Count" at 188.197,95.491 h3
  text "Hole Size" at 201.482,95.491 h3
  text "Plated" at 224.389,95.491 h3
  text "Hole Type" at 234.705,95.491 h3
  text "Drill Layer Pair" at 249.725,95.491 h3
  text "Via/Pad" at 278.192,95.491 h3
  text "Hole Length" at 290.499,95.491 h3
  text "Routed Path Length" at 312.121,95.491 h3
  text "1099" at 188.197,90.314 h2.5
  text "0,20mm (7,87mil)" at 201.482,90.314 h2.5
  text "PTH" at 224.389,90.314 h2.5
  text "Round" at 234.705,90.314 h2.5
  text "Top Layer - Bottom Layer" at 249.725,90.314 h2.5
  text "Via" at 278.192,90.314 h2.5
  text "-" at 290.499,90.314 h2.5
  text "-" at 312.121,90.314 h2.5
  text "9" at 188.197,85.136 h2.5
  text "0,30mm (11,81mil)" at 201.482,85.136 h2.5
  text "PTH" at 224.389,85.136 h2.5
  text "Round" at 234.705,85.136 h2.5
  text "Top Layer - Bottom Layer" at 249.725,85.136 h2.5
  text "Via" at 278.192,85.136 h2.5
  text "-" at 290.499,85.136 h2.5
  text "-" at 312.121,85.136 h2.5
  text "4" at 188.197,79.959 h2.5
  text "0,60mm (23,62mil)" at 201.482,79.959 h2.5
  text "PTH" at 224.389,79.959 h2.5
  text "Slot" at 234.705,79.959 h2.5
  text "Top Layer - Bottom Layer" at 249.725,79.959 h2.5
  text "Pad" at 278.192,79.959 h2.5
  text "1,30mm (51,18mil)" at 290.499,79.959 h2.5
  text "0,70mm (27,56mil)" at 312.121,79.959 h2.5
  text "2" at 188.197,74.781 h2.5
  text "0,65mm (25,59mil)" at 201.482,74.781 h2.5
  text "PTH" at 224.389,74.781 h2.5
  text "Slot" at 234.705,74.781 h2.5
  text "Top Layer - Bottom Layer" at 249.725,74.781 h2.5
  text "Pad" at 278.192,74.781 h2.5
  text "0,85mm (33,47mil)" at 290.499,74.781 h2.5
  text "0,20mm (7,88mil)" at 312.121,74.781 h2.5
  text "A" at 175.504,74.528 h2.3
  text "1" at 188.197,69.604 h2.5
  text "0,65mm (25,59mil)" at 201.482,69.604 h2.5
  text "NPTH" at 224.389,69.604 h2.5
  text "Round" at 234.705,69.604 h2.5
  text "Top Layer - Bottom Layer" at 249.725,69.604 h2.5
  text "Pad" at 278.192,69.604 h2.5
  text "-" at 290.499,69.604 h2.5
  text "-" at 312.121,69.604 h2.5
  text "O" at 175.504,69.35 h2.3
  text "1" at 188.197,64.426 h2.5
  text "0,70mm (27,56mil)" at 201.482,64.426 h2.5
  text "NPTH" at 224.389,64.426 h2.5
  text "Round" at 234.705,64.426 h2.5
  text "Top Layer - Bottom Layer" at 249.725,64.426 h2.5
  text "Pad" at 278.192,64.426 h2.5
  text "-" at 290.499,64.426 h2.5
  text "-" at 312.121,64.426 h2.5
  text "P" at 175.504,64.173 h2.3
  text "32" at 188.197,59.249 h2.5
  text "0,70mm (27,56mil)" at 201.482,59.249 h2.5
  text "PTH" at 224.389,59.249 h2.5
  text "Round" at 234.705,59.249 h2.5
  text "Top Layer - Bottom Layer" at 249.725,59.249 h2.5
  text "Pad" at 278.192,59.249 h2.5
  text "-" at 290.499,59.249 h2.5
  text "-" at 312.121,59.249 h2.5
  text "2" at 188.197,54.071 h2.5
  text "0,70mm (27,56mil)" at 201.482,54.071 h2.5
  text "PTH" at 224.389,54.071 h2.5
  text "Slot" at 234.705,54.071 h2.5
  text "Top Layer - Bottom Layer" at 249.725,54.071 h2.5
  text "Pad" at 278.192,54.071 h2.5
  text "2,20mm (86,61mil)" at 290.499,54.071 h2.5
  text "1,50mm (59,06mil)" at 312.121,54.071 h2.5
  text "2" at 188.197,48.894 h2.5
  text "0,85mm (33,47mil)" at 201.482,48.894 h2.5
  text "NPTH" at 224.389,48.894 h2.5
  text "Slot" at 234.705,48.894 h2.5
  text "Top Layer - Bottom Layer" at 249.725,48.894 h2.5
  text "Pad" at 278.192,48.894 h2.5
  text "2,42mm (95,47mil)" at 290.499,48.894 h2.5
  text "1,58mm (62,01mil)" at 312.121,48.894 h2.5
  text "25" at 188.197,43.717 h2.5
  text "0,90mm (35,43mil)" at 201.482,43.717 h2.5
  text "PTH" at 224.389,43.717 h2.5
  text "Round" at 234.705,43.717 h2.5
  text "Top Layer - Bottom Layer" at 249.725,43.717 h2.5
  text "Pad" at 278.192,43.717 h2.5
  text "-" at 290.499,43.717 h2.5
  text "-" at 312.121,43.717 h2.5
  text "2" at 188.197,38.539 h2.5
  text "0,97mm (38,19mil)" at 201.482,38.539 h2.5
  text "NPTH" at 224.389,38.539 h2.5
  text "Round" at 234.705,38.539 h2.5
  text "Top Layer - Bottom Layer" at 249.725,38.539 h2.5
  text "Pad" at 278.192,38.539 h2.5
  text "-" at 290.499,38.539 h2.5
  text "-" at 312.121,38.539 h2.5
  text "26" at 188.197,33.362 h2.5
  text "1,00mm (39,37mil)" at 201.482,33.362 h2.5
  text "PTH" at 224.389,33.362 h2.5
  text "Round" at 234.705,33.362 h2.5
  text "Top Layer - Bottom Layer" at 249.725,33.362 h2.5
  text "Pad" at 278.192,33.362 h2.5
  text "-" at 290.499,33.362 h2.5
  text "-" at 312.121,33.362 h2.5
  text "3" at 188.197,28.184 h2.5
  text "1,10mm (43,31mil)" at 201.482,28.184 h2.5
  text "NPTH" at 224.389,28.184 h2.5
  text "Round" at 234.705,28.184 h2.5
  text "Top Layer - Bottom Layer" at 249.725,28.184 h2.5
  text "Pad" at 278.192,28.184 h2.5
  text "-" at 290.499,28.184 h2.5
  text "-" at 312.121,28.184 h2.5
  text "F" at 175.504,27.931 h2.3
  text "22" at 188.197,23.007 h2.5
  text "1,10mm (43,31mil)" at 201.482,23.007 h2.5
  text "PTH" at 224.389,23.007 h2.5
  text "Round" at 234.705,23.007 h2.5
  text "Top Layer - Bottom Layer" at 249.725,23.007 h2.5
  text "Pad" at 278.192,23.007 h2.5
  text "-" at 290.499,23.007 h2.5
  text "-" at 312.121,23.007 h2.5
  text "M" at 175.504,22.753 h2.3
  text "2" at 188.197,17.829 h2.5
  text "1,19mm (46,85mil)" at 201.482,17.829 h2.5
  text "NPTH" at 224.389,17.829 h2.5
  text "Round" at 234.705,17.829 h2.5
  text "Top Layer - Bottom Layer" at 249.725,17.829 h2.5
  text "Pad" at 278.192,17.829 h2.5
  text "-" at 290.499,17.829 h2.5
  text "-" at 312.121,17.829 h2.5
  text "L" at 175.504,17.576 h2.3
  text "4" at 188.197,12.652 h2.5
  text "2,00mm (78,74mil)" at 201.482,12.652 h2.5
  text "NPTH" at 224.389,12.652 h2.5
  text "Round" at 234.705,12.652 h2.5
  text "Top Layer - Bottom Layer" at 249.725,12.652 h2.5
  text "Pad" at 278.192,12.652 h2.5
  text "-" at 290.499,12.652 h2.5
  text "-" at 312.121,12.652 h2.5
  text "B" at 175.504,12.398 h2.3
  text "4" at 188.197,7.475 h2.5
  text "3,50mm (137,79mil)" at 201.482,7.475 h2.5
  text "PTH" at 224.389,7.475 h2.5
  text "Round" at 234.705,7.475 h2.5
  text "Top Layer - Bottom Layer" at 249.725,7.475 h2.5
  text "Pad" at 278.192,7.475 h2.5
  text "-" at 290.499,7.475 h2.5
  text "-" at 312.121,7.475 h2.5
  text "E" at 175.504,7.221 h2.3
  text "2" at 188.197,2.297 h2.5
  text "4,50mm (177,17mil)" at 201.482,2.297 h2.5
  text "PTH" at 224.389,2.297 h2.5
  text "Round" at 234.705,2.297 h2.5
  text "Top Layer - Bottom Layer" at 249.725,2.297 h2.5
  text "Pad" at 278.192,2.297 h2.5
  text "-" at 290.499,2.297 h2.5
  text "-" at 312.121,2.297 h2.5
  text "Q" at 175.504,2.043 h2.3
  text "1242 Total" at 188.197,-2.88 h2.5
  text "Slot definitions :" at 176.445,-6.505 h2.5
  text "Routed Path Length" at 193.506,-6.505 h2.5
  text "= Calculated from tool start centre position to tool end centre position." at 214.642,-6.505 h2.5
  text "Hole Length" at 193.506,-8.576 h2.5
  text "= Routed Path Length + Tool Size = Slot length as defined in the PCB layout" at 206.796,-8.576 h2.5
  text ".Layer_Name" at 36.253,-23.408 h3
  text ".DRL" at 77.948,-23.408 h3
M20-Top Title Box:
  circle w0.254: c114.258,-30.129 r1.3
  region: 99.78,-31.222 89.024,-31.222 90.017,-28.729 97.875,-28.729 98.323,-27.97 100.532,-30.518
  region: 113.783,-22.892 98.256,-22.892 97.561,-24.668 96.351,-25.893 94.954,-24.033 94.954,-22.382 96.097,-20.985 97.533,-20.606 113.783,-20.606
  lines w0.254: 90.017,-28.729 98.809,-28.729 95.743,-25.191 cw(c97.546,-23.247) 97.787,-20.606 114.551,-20.606 113.789,-22.892 ; 93.331,-20.359 cw(c95.757,-21.33) 95.993,-18.727 ; 93.37,-20.327 89.024,-31.222 108.346,-31.222 ccw(c108.595,-28.487) 111.144,-29.507 ; 95.11,-24.261 100.532,-30.518 ; 95.364,-24.261 100.669,-30.383 ; 95.364,-24.007 100.669,-30.129 ; 95.462,-22.892 108.455,-22.892 ; 95.491,-23.88 100.796,-30.002 ; 95.618,-23.753 100.923,-29.875 ; 95.745,-23.626 101.05,-29.748 ; 95.872,-23.499 101.177,-29.621 ; 95.926,-21.547 101.231,-27.668 ; 95.995,-18.727 115.444,-18.727 111.145,-29.505 ; 95.999,-23.372 101.249,-29.431 ; 95.999,-23.118 101.304,-29.24 ; 95.999,-22.864 101.304,-28.986 ; 95.999,-21.975 101.304,-28.097 ; 96.126,-22.737 101.431,-28.859 ; 96.126,-22.356 101.431,-28.478 ; 97.497,-28.742 ccw(c97.602,-28.207) 97.9,-27.75 ; 98.584,-22.879 ccw(c98.558,-23.446) 98.228,-23.908 100.592,-26.637 cw(c98.789,-28.581) 99.521,-31.129 ; 104.865,-31.018 107.754,-22.638 ; 105.087,-30.968 107.957,-22.647 ; 105.214,-30.968 108.084,-22.647 ; 105.468,-30.968 108.338,-22.647 ; 105.722,-30.968 108.592,-22.647 ; 105.976,-30.968 108.846,-22.647 ; 106.23,-30.968 109.1,-22.647 ; 106.484,-30.968 109.354,-22.647 ; 106.738,-30.968 109.608,-22.647 ; 106.992,-30.968 109.862,-22.647 ; 107.201,-31.018 110.09,-22.638 ; 110.09,-22.892 113.783,-22.892 ; 113.115,-22.89 113.877,-20.604 ; 113.281,-22.892 114.043,-20.606 ; 113.535,-22.892 114.297,-20.606
  lines w0.3: 27.253,-35.108 117.253,-35.108 117.253,-15.108 27.253,-15.108 ; 27.253,-30.108 87.253,-30.108 ; 27.253,-25.108 87.253,-25.108 ; 27.253,-20.108 87.253,-20.108 ; 27.254,-35.108 27.254,-15.108 ; 67.253,-35.108 67.253,-20.108 ; 87.253,-35.108 87.253,-15.108 ; 104.865,-31.018 107.201,-31.018
  text "Project: '.Board_Name'" at 28.253,-18.324 h3
  text "Layer:" at 28.254,-23.408 h3
  text "Gerber:" at 68.242,-23.408 h3
  text "Variant: '.VariantName'" at 28.253,-28.408 h3
  text "'.Board_Reference'" at 68.369,-28.408 h3
  text "R" at 113.75,-30.891 h1.52
  text "Date: '.Board_Document_Date'" at 28.253,-33.408 h3
  text "Rev: '.Board_PCB_Revision'" at 68.312,-33.408 h3
M21-Bottom Title Box:
  circle w0.254: c30.436,-30.129 r1.3
  region: 30.911,-22.892 46.438,-22.892 47.132,-24.668 48.343,-25.893 49.74,-24.033 49.74,-22.382 48.597,-20.985 47.161,-20.606 30.911,-20.606
  region: 44.914,-31.222 55.67,-31.222 54.677,-28.729 46.819,-28.729 46.37,-27.97 44.162,-30.518
  lines w0.254: 30.397,-20.606 31.159,-22.892 ; 30.651,-20.606 31.413,-22.892 ; 30.817,-20.604 31.579,-22.89 ; 30.905,-22.892 30.143,-20.606 46.907,-20.606 cw(c47.147,-23.247) 48.951,-25.191 45.885,-28.729 54.677,-28.729 ; 30.911,-22.892 34.603,-22.892 ; 33.549,-29.505 29.249,-18.727 48.699,-18.727 ; 33.55,-29.507 ccw(c36.099,-28.487) 36.347,-31.222 55.67,-31.222 51.324,-20.327 ; 34.603,-22.638 37.493,-31.018 ; 34.832,-22.647 37.701,-30.968 ; 35.086,-22.647 37.955,-30.968 ; 35.34,-22.647 38.209,-30.968 ; 35.594,-22.647 38.463,-30.968 ; 35.848,-22.647 38.717,-30.968 ; 36.102,-22.647 38.971,-30.968 ; 36.239,-22.892 49.232,-22.892 ; 36.356,-22.647 39.225,-30.968 ; 36.61,-22.647 39.479,-30.968 ; 36.737,-22.647 39.606,-30.968 ; 36.939,-22.638 39.829,-31.018 ; 43.263,-28.859 48.568,-22.737 ; 43.263,-28.478 48.568,-22.356 ; 43.39,-29.24 48.695,-23.118 ; 43.39,-28.986 48.695,-22.864 ; 43.39,-28.097 48.695,-21.975 ; 43.445,-29.431 48.695,-23.372 ; 43.462,-27.668 48.767,-21.547 ; 43.517,-29.621 48.822,-23.499 ; 43.644,-29.748 48.949,-23.626 ; 43.771,-29.875 49.076,-23.753 ; 43.898,-30.002 49.203,-23.88 ; 44.025,-30.383 49.33,-24.261 ; 44.025,-30.129 49.33,-24.007 ; 44.162,-30.518 49.584,-24.261 ; 45.172,-31.129 cw(c45.905,-28.581) 44.101,-26.637 46.466,-23.908 ccw(c46.136,-23.446) 46.11,-22.879 ; 46.794,-27.75 ccw(c47.091,-28.207) 47.196,-28.742 ; 48.7,-18.727 cw(c48.937,-21.33) 51.363,-20.359
  lines w0.3: 37.493,-31.018 39.829,-31.018 ; 57.253,-35.108 57.253,-15.108 ; 57.253,-30.108 117.253,-30.108 ; 57.253,-25.108 117.253,-25.108 ; 57.253,-20.108 117.253,-20.108 ; 77.253,-35.108 77.253,-20.108 ; 27.253,-35.108 27.253,-15.108 117.253,-15.108 117.253,-35.108 27.253,-35.108
  text "Project: '.Board_Name'" at 116.059,-18.324 h3
  text "Gerber:" at 76.07,-23.408 h3
  text "Layer:" at 116.059,-23.408 h3
  text "'.Board_Reference'" at 76.07,-28.408 h3
  text "Variant: '.VariantName'" at 116.059,-28.408 h3
  text "R" at 30.944,-30.891 h1.52
  text "Rev: '.Board_PCB_Revision'" at 76.127,-33.408 h3
  text "Date: '.Board_Document_Date'" at 116.059,-33.408 h3

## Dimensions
0,86 to 159,86 on M2-Board Dimensions
2,0 to 2,88 on M2-Board Dimensions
